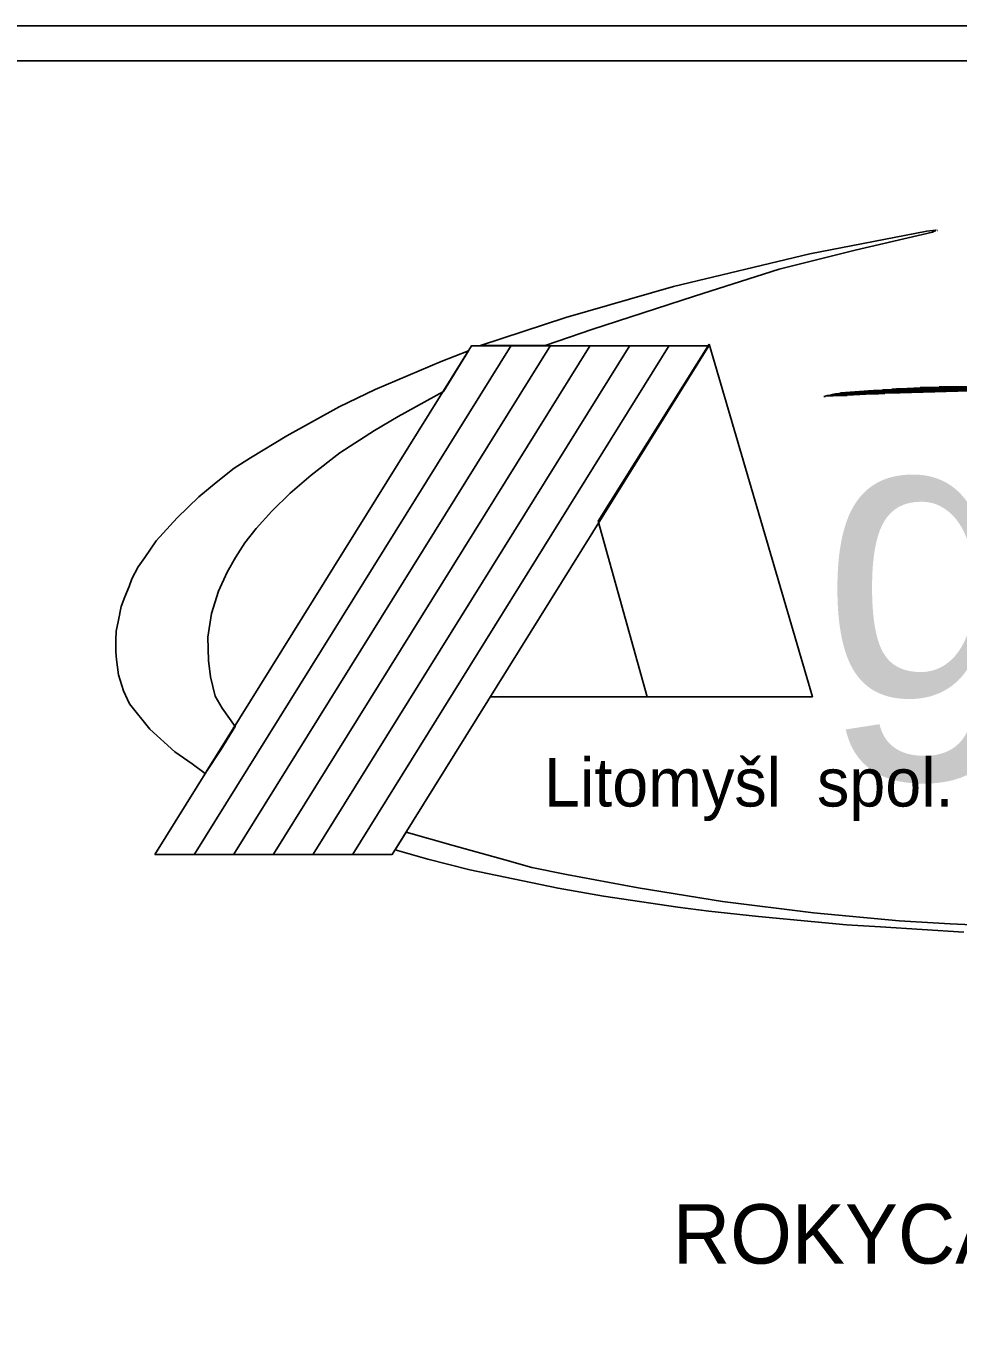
# Model space of a CAD drawing. Extents: x -706655 to -706193, y -1036183 to -1035040.
# Drawn here: x -706319.52 to -706307.75, y -1035257.32 to -1035240.93 of the extents above; entities that cross this region are included whole.
import ezdxf

# ---------------------------------------------------------------- set-up
doc = ezdxf.new("R2010")
doc.units = 0
doc.layers.add('Vrstva 54', color=7, linetype='Continuous')

msp = doc.modelspace()

# ---------------------------------------------------------------- linework, layer by layer
at = {"layer": 'Vrstva 54'}
for p, q in [((-706308.039, -1035243.516), (-706308.034, -1035243.516)), ((-706308.017, -1035243.511), (-706308.015, -1035243.511)), ((-706317.395, -1035251.383), (-706313.398, -1035244.965)), ((-706316.898, -1035251.383), (-706312.899, -1035244.965)), ((-706316.396, -1035251.383), (-706312.399, -1035244.965)), ((-706315.896, -1035251.383), (-706311.899, -1035244.965)), ((-706315.896, -1035251.383), (-706311.899, -1035244.965)), ((-706315.396, -1035251.383), (-706311.4, -1035244.965)), ((-706309.365, -1035245.588), (-706309.074, -1035245.588)), ((-706309.344, -1035245.584), (-706308.995, -1035245.584)), ((-706309.322, -1035245.58), (-706308.917, -1035245.58)), ((-706309.302, -1035245.576), (-706308.836, -1035245.576)), ((-706309.28, -1035245.572), (-706308.757, -1035245.572)), ((-706309.259, -1035245.568), (-706308.678, -1035245.568)), ((-706309.237, -1035245.563), (-706308.598, -1035245.563)), ((-706309.218, -1035245.561), (-706308.486, -1035245.561)), ((-706309.174, -1035245.556), (-706308.34, -1035245.556)), ((-706309.115, -1035245.554), (-706308.194, -1035245.554)), ((-706309.057, -1035245.549), (-706308.048, -1035245.549)), ((-706309, -1035245.545), (-706307.902, -1035245.545)), ((-706308.94, -1035245.542), (-706307.756, -1035245.542)), ((-706308.883, -1035245.538), (-706307.474, -1035245.538)), ((-706308.823, -1035245.533), (-706307.055, -1035245.533)), ((-706308.765, -1035245.53), (-706303.023, -1035245.53)), ((-706308.708, -1035245.524), (-706303.081, -1035245.524)), ((-706308.649, -1035245.522), (-706303.138, -1035245.522)), ((-706308.591, -1035245.517), (-706303.199, -1035245.517)), ((-706308.532, -1035245.511), (-706303.258, -1035245.511)), ((-706308.475, -1035245.509), (-706303.315, -1035245.509)), ((-706308.395, -1035245.505), (-706303.395, -1035245.505)), ((-706308.314, -1035245.502), (-706303.476, -1035245.502)), ((-706308.234, -1035245.496), (-706303.557, -1035245.496)), ((-706308.153, -1035245.492), (-706303.637, -1035245.492)), ((-706307.992, -1035245.485), (-706303.796, -1035245.485)), ((-706309.447, -1035245.606), (-706309.427, -1035245.606)), ((-706309.427, -1035245.6), (-706309.332, -1035245.6)), ((-706309.406, -1035245.595), (-706309.237, -1035245.595)), ((-706309.386, -1035245.593), (-706309.153, -1035245.593)), ((-706313.664, -1035249.4), (-706311.681, -1035249.4)), ((-706317.246, -1035250.346), (-706316.898, -1035249.785))]:
    msp.add_line(p, q, dxfattribs=at)
for points in [[(-706378.89, -1035240.93), (-706291.39, -1035240.93), (-706291.39, -1035280.93), (-706378.89, -1035280.93)], [(-706378.289, -1035241.37), (-706291.789, -1035241.37), (-706291.789, -1035280.37), (-706378.289, -1035280.37)], [(-706313.784, -1035244.965), (-706312.704, -1035244.609), (-706311.345, -1035244.219), (-706309.624, -1035243.808), (-706308.15, -1035243.521), (-706308.033, -1035243.507), (-706308.075, -1035243.535), (-706309.052, -1035243.76), (-706310.011, -1035244.001), (-706311.081, -1035244.341), (-706312.379, -1035244.764), (-706312.955, -1035244.959)], [(-706317.26, -1035250.365), (-706317.422, -1035250.246), (-706317.641, -1035250.092), (-706317.96, -1035249.808), (-706318.215, -1035249.486), (-706318.29, -1035249.324), (-706318.353, -1035249.121), (-706318.38, -1035248.927), (-706318.388, -1035248.83), (-706318.388, -1035248.684), (-706318.384, -1035248.569), (-706318.353, -1035248.43), (-706318.321, -1035248.257), (-706318.274, -1035248.135), (-706318.219, -1035248.005), (-706318.184, -1035247.91), (-706318.105, -1035247.756), (-706318.022, -1035247.641), (-706317.877, -1035247.43), (-706317.614, -1035247.14), (-706317.339, -1035246.875), (-706317.119, -1035246.693), (-706316.895, -1035246.513), (-706316.687, -1035246.38), (-706316.228, -1035246.102), (-706315.568, -1035245.739), (-706315.112, -1035245.521), (-706314.28, -1035245.166), (-706313.934, -1035245.033), (-706314.252, -1035245.546), (-706314.822, -1035245.859), (-706315.123, -1035246.037), (-706315.56, -1035246.317), (-706315.921, -1035246.6), (-706316.185, -1035246.827), (-706316.417, -1035247.053), (-706316.617, -1035247.275), (-706316.758, -1035247.456), (-706316.876, -1035247.638), (-706316.982, -1035247.825), (-706317.092, -1035248.064), (-706317.178, -1035248.346), (-706317.225, -1035248.644), (-706317.218, -1035248.939), (-706317.194, -1035249.146), (-706317.135, -1035249.392), (-706317.045, -1035249.543), (-706316.88, -1035249.771), (-706317.061, -1035250.069)], [(-706310.895, -1035244.946), (-706309.592, -1035249.398), (-706311.681, -1035249.4), (-706312.298, -1035247.18)]]:
    msp.add_lwpolyline(points, close=True, dxfattribs=at)
for points in [[(-706317.897, -1035251.388), (-706314.898, -1035251.388), (-706310.9, -1035244.969), (-706313.898, -1035244.969), (-706317.897, -1035251.388)], [(-706316.898, -1035249.785), (-706316.903, -1035249.779)], [(-706317.252, -1035250.341), (-706317.246, -1035250.346)], [(-706307.03, -1035252.301), (-706307.855, -1035252.262), (-706308.498, -1035252.227), (-706309.581, -1035252.126), (-706310.727, -1035251.983), (-706311.792, -1035251.811), (-706312.697, -1035251.643), (-706313.134, -1035251.551), (-706313.475, -1035251.457), (-706314.128, -1035251.277), (-706314.721, -1035251.108), (-706314.862, -1035251.33), (-706314.448, -1035251.446), (-706313.918, -1035251.583), (-706312.803, -1035251.815), (-706312.231, -1035251.914), (-706311.294, -1035252.053), (-706310.901, -1035252.103), (-706310.274, -1035252.172), (-706309.561, -1035252.239), (-706309.162, -1035252.276), (-706308.735, -1035252.302), (-706307.679, -1035252.367)]]:
    msp.add_lwpolyline(points, dxfattribs=at)

# ---------------------------------------------------------------- texts
for s, height, p in [('groprojekce', 3.60691, (-706309.48, -1035249.406)), ('Litomyšl  spol. s.r.o.', 0.61041, (-706312.982, -1035250.783)), (' ROKYCANOVA 114/IV', 0.75, (-706311.634, -1035256.553))]:
    msp.add_text(s, height=height, rotation=0, dxfattribs=at).set_placement(p)

doc.saveas('drawing.dxf')
